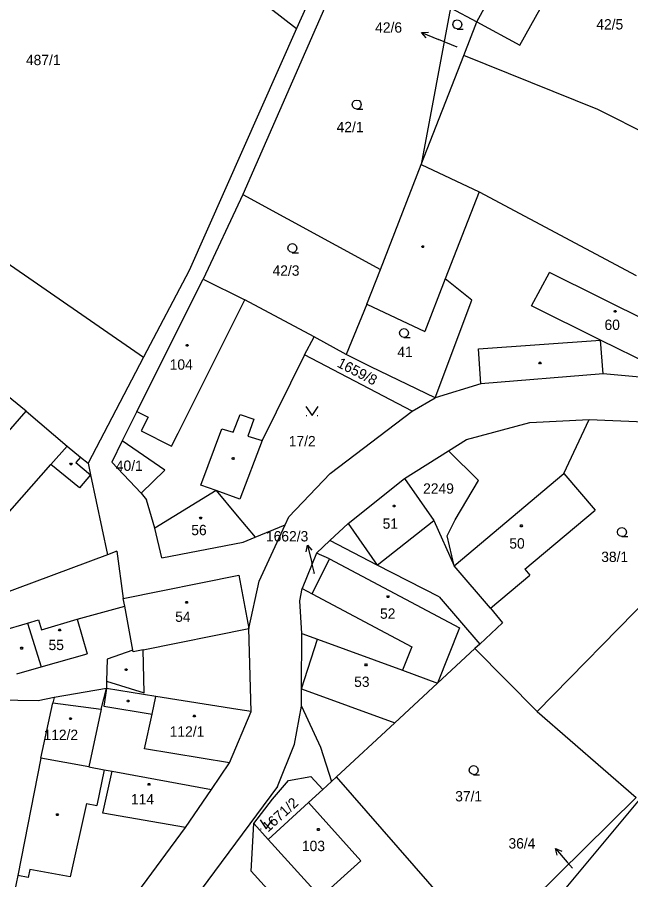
# Model space of a CAD drawing. Extents: x -802857 to -799647, y -1020285 to -1015884.
# Drawn here: x -801708.7 to -801607.8, y -1017782.1 to -1017640.2 of the extents above; entities that cross this region are included whole.
import ezdxf

# ---------------------------------------------------------------- set-up
doc = ezdxf.new("R2010")
doc.units = 0
for name, color, linetype in [('Default', 7, 'Continuous'), ('KN_HRANICE', 7, 'Continuous'), ('KN_KULTURY', 7, 'Continuous'), ('KN_PARCELY', 7, 'Continuous'), ('KN_SLUCKY', 7, 'Continuous')]:
    doc.layers.add(name, color=color, linetype=linetype)

# ---------------------------------------------------------------- blocks, each defined once
blk = doc.blocks.new('304')
at = {"layer": 'Default'}
blk.add_lwpolyline([(0, 0), (-0.38, 0.1), (-0.65, 0.37), (-0.75, 0.74), (-0.65, 1.11), (-0.38, 1.38), (-0.01, 1.48), (0.36, 1.38), (0.63, 1.11), (0.73, 0.73), (0.63, 0.35), (0.36, 0.08), (-0.02, -0.02), (0.98, -0.02)], dxfattribs=at)
blk = doc.blocks.new('314')
at = {"layer": 'Default'}
for p, q in [((-0.95, 0), (-0.85, 0)), ((0.85, 0), (0.95, 0))]:
    blk.add_line(p, q, dxfattribs=at)
blk.add_lwpolyline([(-1, 1.5), (0, 0), (1, 1.5)], dxfattribs=at)
blk = doc.blocks.new('NAHRADNI_SYMBOL')
at = {"layer": 'Default'}
blk.add_lwpolyline([(0.09, 0.15), (0.18, 0), (0.09, -0.15), (-0.09, -0.15), (-0.18, 0), (-0.09, 0.15), (0.09, 0.15)], dxfattribs=at)
blk = doc.blocks.new('10292')
at = {"layer": 'Default'}
blk.add_line((0, 3), (0, 0), dxfattribs=at)
blk.add_lwpolyline([(-0.5, 2), (0, 3), (0.5, 2)], dxfattribs=at)
blk = doc.blocks.new('402')
at = {"layer": 'Default'}
blk.add_lwpolyline([(0.09, 0.15), (0.18, 0), (0.09, -0.15), (-0.09, -0.15), (-0.18, 0), (-0.09, 0.15), (0.09, 0.15)], dxfattribs=at)

msp = doc.modelspace()

# ---------------------------------------------------------------- linework, layer by layer
at = {"layer": 'KN_HRANICE'}
for p, q in [((-801694.39, -1017617.48), (-801662.74, -1017642.08)), ((-801654.11, -1017629.4), (-801671.57, -1017669.41)), ((-801626.01, -1017644.85), (-801618.78, -1017631.82)), ((-801659.97, -1017635.92), (-801662.74, -1017642.08)), ((-801637.41, -1017638.71), (-801642.23, -1017664.46)), ((-801637.41, -1017638.71), (-801633.09, -1017641.02)), ((-801635.24, -1017646.54), (-801633.09, -1017641.02)), ((-801633.09, -1017641.02), (-801626.01, -1017644.85)), ((-801662.74, -1017642.08), (-801680.42, -1017681.9)), ((-801642.23, -1017664.46), (-801635.24, -1017646.54)), ((-801613.19, -1017655.4), (-801635.24, -1017646.54)), ((-801746.02, -1017656.03), (-801687.92, -1017696.18)), ((-801602.44, -1017660.83), (-801613.19, -1017655.4)), ((-801648.97, -1017681.75), (-801642.23, -1017664.46)), ((-801642.23, -1017664.46), (-801632.7, -1017668.98)), ((-801671.57, -1017669.41), (-801678.12, -1017683.31)), ((-801671.57, -1017669.41), (-801648.97, -1017681.75)), ((-801632.7, -1017668.98), (-801606.86, -1017682.7)), ((-801680.42, -1017681.9), (-801687.92, -1017696.18)), ((-801651.19, -1017687.43), (-801648.97, -1017681.75)), ((-801689.02, -1017705.11), (-801678.12, -1017683.31)), ((-801678.12, -1017683.31), (-801671.27, -1017686.73)), ((-801638.28, -1017683.28), (-801641.66, -1017691.95)), ((-801633.9, -1017686.78), (-801638.28, -1017683.28)), ((-801659.87, -1017692.82), (-801671.27, -1017686.73)), ((-801639.95, -1017702.84), (-801633.9, -1017686.78)), ((-801651.19, -1017687.43), (-801654.58, -1017695.71)), ((-801651.19, -1017687.43), (-801641.66, -1017691.95)), ((-801661.47, -1017695.76), (-801659.87, -1017692.82)), ((-801654.58, -1017695.71), (-801659.87, -1017692.82)), ((-801661.47, -1017695.76), (-801668.42, -1017709.88)), ((-801643.76, -1017705.03), (-801661.47, -1017695.76)), ((-801650.51, -1017697.72), (-801654.58, -1017695.71)), ((-801687.92, -1017696.18), (-801697.06, -1017713.57)), ((-801707.22, -1017705.04), (-801715, -1017698.75)), ((-801639.95, -1017702.84), (-801650.51, -1017697.72)), ((-801612.31, -1017698.9), (-801632.42, -1017700.52)), ((-801599.1, -1017700.11), (-801612.31, -1017698.9)), ((-801632.42, -1017700.52), (-801639.95, -1017702.84)), ((-801643.76, -1017705.03), (-801639.95, -1017702.84)), ((-801707.22, -1017705.04), (-801700.51, -1017710.77)), ((-801689.02, -1017705.11), (-801691.42, -1017709.92)), ((-801657.25, -1017715.27), (-801643.76, -1017705.03)), ((-801634.78, -1017709.68), (-801624.37, -1017706.9)), ((-801624.37, -1017706.9), (-801614.64, -1017706.43)), ((-801618.81, -1017715.29), (-801614.64, -1017706.43)), ((-801614.64, -1017706.43), (-801605.52, -1017706.8)), ((-801691.42, -1017709.92), (-801693.16, -1017713.42)), ((-801684.4, -1017714.76), (-801691.42, -1017709.92)), ((-801668.42, -1017709.88), (-801672.08, -1017719.51)), ((-801637.74, -1017711.55), (-801634.78, -1017709.68)), ((-801700.51, -1017710.77), (-801698.31, -1017712.61)), ((-801698.31, -1017712.61), (-801697.06, -1017713.57)), ((-801644.97, -1017716.12), (-801637.74, -1017711.55)), ((-801632.83, -1017716.42), (-801637.74, -1017711.55)), ((-801697.06, -1017713.57), (-801696.65, -1017715.5)), ((-801693.16, -1017713.42), (-801688.31, -1017718.52)), ((-801696.65, -1017715.5), (-801693.84, -1017728.66)), ((-801688.31, -1017718.52), (-801684.4, -1017714.76)), ((-801664.02, -1017722.44), (-801657.25, -1017715.27)), ((-801618.81, -1017715.29), (-801613.64, -1017721.3)), ((-801654.28, -1017723.49), (-801644.97, -1017716.12)), ((-801644.97, -1017716.12), (-801640.18, -1017723)), ((-801636.65, -1017722.91), (-801632.83, -1017716.42)), ((-801688.31, -1017718.52), (-801687.42, -1017719.63)), ((-801676, -1017718.11), (-801686.05, -1017724.27)), ((-801676, -1017718.11), (-801672.54, -1017722.24)), ((-801672.08, -1017719.51), (-801676, -1017718.11)), ((-801686.05, -1017724.27), (-801687.42, -1017719.63)), ((-801625.19, -1017731.05), (-801613.64, -1017721.3)), ((-801672.54, -1017722.24), (-801669.57, -1017725.78)), ((-801664.62, -1017723.74), (-801664.02, -1017722.44)), ((-801684.89, -1017729.17), (-801686.05, -1017724.27)), ((-801669.57, -1017725.78), (-801664.62, -1017723.74)), ((-801668.93, -1017733.02), (-801664.62, -1017723.74)), ((-801657.27, -1017726.33), (-801654.28, -1017723.49)), ((-801640.18, -1017723), (-801636.81, -1017730.48)), ((-801637.99, -1017725.54), (-801636.65, -1017722.91)), ((-801636.81, -1017730.48), (-801637.99, -1017725.54)), ((-801684.89, -1017729.17), (-801671.54, -1017726.59)), ((-801671.54, -1017726.59), (-801669.57, -1017725.78)), ((-801659.45, -1017728.4), (-801657.27, -1017726.33)), ((-801649.49, -1017730.37), (-801657.27, -1017726.33)), ((-801692.32, -1017728.09), (-801693.84, -1017728.66)), ((-801692.32, -1017728.09), (-801691.26, -1017735.85)), ((-801659.45, -1017728.4), (-801661.85, -1017734.23)), ((-801657.36, -1017729.32), (-801659.45, -1017728.4)), ((-801597.05, -1017727.73), (-801623.18, -1017754.46)), ((-801693.84, -1017728.66), (-801719.81, -1017738.32)), ((-801660.18, -1017735.09), (-801657.36, -1017729.32)), ((-801639.32, -1017735.57), (-801649.49, -1017730.37)), ((-801630.84, -1017737.46), (-801636.81, -1017730.48)), ((-801625.19, -1017731.05), (-801624.39, -1017732.01)), ((-801691.26, -1017735.85), (-801672.26, -1017732.02)), ((-801672.26, -1017732.02), (-801670.61, -1017740.8)), ((-801630.84, -1017737.46), (-801624.39, -1017732.01)), ((-801670.61, -1017740.8), (-801668.93, -1017733.02)), ((-801662.24, -1017736.26), (-801661.85, -1017734.23)), ((-801661.85, -1017734.23), (-801660.18, -1017735.09)), ((-801639.32, -1017735.57), (-801632.63, -1017743.34)), ((-801691.02, -1017737.09), (-801691.26, -1017735.85)), ((-801661.88, -1017741.62), (-801662.24, -1017736.26)), ((-801698.82, -1017739.23), (-801691.02, -1017737.09)), ((-801689.66, -1017744.35), (-801691.02, -1017737.09)), ((-801630.84, -1017737.46), (-801628.85, -1017739.85)), ((-801711.1, -1017741.13), (-801707, -1017739.9)), ((-801707, -1017739.9), (-801705.23, -1017739.37)), ((-801705.23, -1017739.37), (-801704.71, -1017740.98)), ((-801704.71, -1017740.98), (-801698.82, -1017739.23)), ((-801628.85, -1017739.85), (-801632.63, -1017743.34)), ((-801670.22, -1017754.45), (-801670.61, -1017740.8)), ((-801661.93, -1017750.69), (-801661.88, -1017741.62)), ((-801661.88, -1017741.62), (-801659.31, -1017742.56)), ((-801659.31, -1017742.56), (-801645.35, -1017747.65)), ((-801633.4, -1017744.06), (-801639.56, -1017749.76)), ((-801632.63, -1017743.34), (-801633.4, -1017744.06)), ((-801633.4, -1017744.06), (-801623.18, -1017754.46)), ((-801689.66, -1017744.35), (-801693.92, -1017745.81)), ((-801693.92, -1017745.81), (-801694.01, -1017749.47)), ((-801587.49, -1017746.18), (-801629.02, -1017796.14)), ((-801645.35, -1017747.65), (-801639.56, -1017749.76)), ((-801694.01, -1017749.47), (-801694.04, -1017750.65)), ((-801639.56, -1017749.76), (-801646.6, -1017756.28)), ((-801694.04, -1017750.65), (-801702.65, -1017752.12)), ((-801694.87, -1017754.03), (-801694.04, -1017750.65)), ((-801685.92, -1017751.95), (-801694.04, -1017750.65)), ((-801661.95, -1017753.57), (-801661.93, -1017750.69)), ((-801705.26, -1017752.69), (-801716.23, -1017752.46)), ((-801702.65, -1017752.12), (-801705.26, -1017752.69)), ((-801702.65, -1017752.12), (-801702.84, -1017753.01)), ((-801672.43, -1017754.12), (-801685.92, -1017751.95)), ((-801704.8, -1017762.14), (-801702.84, -1017753.01)), ((-801694.87, -1017754.03), (-801696.92, -1017763.53)), ((-801663.09, -1017759.81), (-801661.95, -1017753.57)), ((-801661.95, -1017753.57), (-801658.82, -1017760.33)), ((-801673.8, -1017762.87), (-801670.22, -1017754.45)), ((-801670.22, -1017754.45), (-801672.43, -1017754.12)), ((-801623.18, -1017754.46), (-801606.88, -1017768.59)), ((-801646.6, -1017756.28), (-801656.2, -1017765.17)), ((-801665.9, -1017766.77), (-801663.09, -1017759.81)), ((-801658.82, -1017760.33), (-801657.03, -1017765.95)), ((-801704.8, -1017762.14), (-801708.61, -1017781.39)), ((-801696.92, -1017763.53), (-801704.8, -1017762.14)), ((-801696.92, -1017763.53), (-801694.4, -1017764.02)), ((-801694.4, -1017764.02), (-801693.09, -1017764.26)), ((-801676.76, -1017767.27), (-801673.8, -1017762.87)), ((-801693.09, -1017764.26), (-801676.76, -1017767.27)), ((-801664.1, -1017765.81), (-801660.39, -1017765.12)), ((-801660.39, -1017765.12), (-801658.43, -1017767.26)), ((-801657.03, -1017765.95), (-801656.2, -1017765.17)), ((-801636.53, -1017787.69), (-801656.2, -1017765.17)), ((-801665.9, -1017766.77), (-801692.56, -1017802.78)), ((-801666.69, -1017768.84), (-801664.1, -1017765.81)), ((-801658.43, -1017767.26), (-801657.03, -1017765.95)), ((-801681, -1017773.54), (-801676.76, -1017767.27)), ((-801658.43, -1017767.26), (-801660.79, -1017769.42)), ((-801669.76, -1017772.89), (-801666.69, -1017768.84)), ((-801667.4, -1017775.47), (-801660.79, -1017769.42)), ((-801606.88, -1017768.59), (-801631.76, -1017793.06)), ((-801694.1, -1017791.18), (-801681, -1017773.54)), ((-801670.22, -1017780.7), (-801669.76, -1017772.89)), ((-801669.76, -1017772.89), (-801667.4, -1017775.47)), ((-801658.84, -1017785), (-801667.4, -1017775.47)), ((-801670.22, -1017780.7), (-801652.82, -1017799.83)), ((-801708.61, -1017781.39), (-801709.16, -1017784.06))]:
    msp.add_line(p, q, dxfattribs=at)
at = {"layer": 'KN_PARCELY'}
for p, q in [((-801636.33, -1017645.16), (-801639.4, -1017643.91)), ((-801659.81, -1017731.72), (-801660.23, -1017729.99)), ((-801617.36, -1017780.23), (-801618.21, -1017779.25))]:
    msp.add_line(p, q, dxfattribs=at)
at = {"layer": 'KN_SLUCKY'}
for p, q in [((-801633.09, -1017641.02), (-801626.1, -1017628.02)), ((-801632.7, -1017668.98), (-801638.28, -1017683.28)), ((-801624.08, -1017687.71), (-801621.15, -1017682.25)), ((-801596.17, -1017694.65), (-801621.15, -1017682.25)), ((-801682.23, -1017708.65), (-801671.27, -1017686.73)), ((-801612.74, -1017693.34), (-801624.08, -1017687.71)), ((-801632.84, -1017694.8), (-801612.74, -1017693.34)), ((-801612.31, -1017698.9), (-801612.74, -1017693.34)), ((-801599.1, -1017700.11), (-801612.74, -1017693.34)), ((-801632.42, -1017700.52), (-801632.84, -1017694.8)), ((-801717.85, -1017717.14), (-801707.22, -1017705.04)), ((-801689.02, -1017705.11), (-801687.18, -1017706.03)), ((-801673.18, -1017708.52), (-801672.05, -1017705.58)), ((-801672.05, -1017705.58), (-801669.78, -1017706.35)), ((-801687.18, -1017706.03), (-801688.31, -1017708.29)), ((-801669.78, -1017706.35), (-801670.76, -1017709.13)), ((-801688.31, -1017708.29), (-801683.3, -1017710.79)), ((-801683.3, -1017710.79), (-801682.23, -1017708.65)), ((-801678.52, -1017717.22), (-801675.04, -1017707.92)), ((-801675.04, -1017707.92), (-801673.18, -1017708.52)), ((-801670.76, -1017709.13), (-801668.42, -1017709.88)), ((-801703.2, -1017713.83), (-801700.51, -1017710.77)), ((-801698.31, -1017712.61), (-801699.07, -1017713.49)), ((-801711.14, -1017722.87), (-801703.2, -1017713.83)), ((-801698.46, -1017717.66), (-801703.2, -1017713.83)), ((-801699.07, -1017713.49), (-801696.65, -1017715.5)), ((-801696.65, -1017715.5), (-801698.46, -1017717.66)), ((-801636.81, -1017730.48), (-801618.81, -1017715.29)), ((-801676, -1017718.11), (-801678.52, -1017717.22)), ((-801654.28, -1017723.49), (-801649.49, -1017730.37)), ((-801649.49, -1017730.37), (-801640.18, -1017723)), ((-801657.36, -1017729.32), (-801635.93, -1017740.7)), ((-801660.18, -1017735.09), (-801643.8, -1017743.79)), ((-801707, -1017739.9), (-801704.74, -1017747.09)), ((-801698.82, -1017739.23), (-801697.22, -1017744.93)), ((-801687.96, -1017744.3), (-801670.61, -1017740.8)), ((-801635.93, -1017740.7), (-801639.56, -1017749.76)), ((-801661.93, -1017750.69), (-801659.31, -1017742.56)), ((-801643.8, -1017743.79), (-801645.35, -1017747.65)), ((-801704.74, -1017747.09), (-801697.22, -1017744.93)), ((-801689.61, -1017744.63), (-801689.66, -1017744.35)), ((-801687.96, -1017744.3), (-801689.61, -1017744.63)), ((-801687.8, -1017751.37), (-801687.96, -1017744.3)), ((-801708.79, -1017748.25), (-801704.74, -1017747.09)), ((-801694.01, -1017749.47), (-801687.8, -1017751.37)), ((-801694.04, -1017750.65), (-801694.46, -1017753.56)), ((-801661.93, -1017750.69), (-801646.6, -1017756.28)), ((-801686.53, -1017754.87), (-801685.92, -1017751.95)), ((-801702.84, -1017753.01), (-801694.87, -1017754.03)), ((-801694.46, -1017753.56), (-801686.53, -1017754.87)), ((-801687.74, -1017760.59), (-801686.53, -1017754.87)), ((-801673.8, -1017762.87), (-801687.74, -1017760.59)), ((-801694.4, -1017764.02), (-801695.62, -1017769.88)), ((-801694.61, -1017771.15), (-801693.09, -1017764.26)), ((-801697.33, -1017769.56), (-801699.98, -1017781.66)), ((-801697.33, -1017769.56), (-801695.62, -1017769.88)), ((-801660.79, -1017769.42), (-801652.2, -1017779.01)), ((-801681, -1017773.54), (-801694.61, -1017771.15)), ((-801652.2, -1017779.01), (-801658.84, -1017785)), ((-801706.65, -1017780.44), (-801706.91, -1017781.74)), ((-801699.98, -1017781.66), (-801706.65, -1017780.44)), ((-801706.91, -1017781.74), (-801708.61, -1017781.39))]:
    msp.add_line(p, q, dxfattribs=at)

# ---------------------------------------------------------------- block references
at = {"layer": 'KN_KULTURY'}
for name, p in [('304', (-801636.31, -1017642.16)), ('304', (-801652.84, -1017655.34)), ('304', (-801663.43, -1017678.95)), ('402', (-801641.99, -1017677.99)), ('402', (-801610.34, -1017688.61)), ('304', (-801645.06, -1017692.91)), ('402', (-801680.74, -1017694.22)), ('402', (-801622.7, -1017697.11)), ('314', (-801660.2, -1017705.75)), ('402', (-801673.19, -1017712.82)), ('402', (-801699.87, -1017713.73)), ('402', (-801646.69, -1017720.65)), ('NAHRADNI_SYMBOL', (-801678.54, -1017722.62)), ('402', (-801625.79, -1017723.89)), ('304', (-801609.23, -1017725.66)), ('402', (-801647.71, -1017735.56)), ('402', (-801680.84, -1017736.48)), ('402', (-801701.71, -1017741.02)), ('402', (-801707.97, -1017744.01)), ('402', (-801651.34, -1017746.77)), ('402', (-801690.78, -1017747.56)), ('402', (-801690.45, -1017752.71)), ('402', (-801699.93, -1017755.62)), ('402', (-801679.56, -1017755.17)), ('304', (-801633.62, -1017764.82)), ('402', (-801687.03, -1017766.41)), ('402', (-801702.11, -1017771.41)), ('314', (-801667.75, -1017773.75)), ('402', (-801659.16, -1017773.85))]:
    msp.add_blockref(name, p, dxfattribs=at)
at = {"layer": 'KN_PARCELY'}
for p, rotation in [((-801639.4, -1017643.91), 67.83820300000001), ((-801660.23, -1017729.99), 13.693691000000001), ((-801618.21, -1017779.25), 40.851890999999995)]:
    msp.add_blockref('10292', p, dxfattribs=dict(at, rotation=rotation))

# ---------------------------------------------------------------- texts
for s, height, p in [('42/5', 1.7, (-801613.44, -1017642.26)), ('42/6', 1.7, (-801649.82, -1017642.78)), ('42/6', 0.1, (-801636.53, -1017645.16)), ('487/1', 1.7, (-801707.27, -1017648.12)), ('42/1', 1.7, (-801656.16, -1017659.15)), ('42/3', 1.7, (-801666.7, -1017682.76)), ('60', 1.7, (-801612.09, -1017691.68)), ('41', 1.7, (-801646.17, -1017696.13)), ('104', 1.7, (-801683.62, -1017698.22)), ('17/2', 1.7, (-801664.03, -1017710.82)), ('40/1', 1.7, (-801692.48, -1017714.86)), ('2249', 1.7, (-801641.93, -1017718.61)), ('51', 1.7, (-801648.59, -1017724.38)), ('56', 1.7, (-801680.07, -1017725.44)), ('1662/3', 1.7, (-801667.78, -1017726.47)), ('50', 1.7, (-801627.75, -1017727.64)), ('38/1', 1.7, (-801612.63, -1017729.85)), ('1662/3', 0.1, (-801660.11, -1017731.72)), ('54', 1.7, (-801682.72, -1017739.7)), ('52', 1.7, (-801649.02, -1017739.19)), ('55', 1.7, (-801703.55, -1017744.34)), ('53', 1.7, (-801653.28, -1017750.4)), ('112/1', 1.7, (-801683.62, -1017758.58)), ('112/2', 1.7, (-801704.38, -1017759.13)), ('114', 1.7, (-801689.99, -1017769.73)), ('37/1', 1.7, (-801636.65, -1017769.23)), ('36/4', 1.7, (-801627.89, -1017776.98)), ('103', 1.7, (-801661.87, -1017777.41)), ('36/4', 0.1, (-801617.56, -1017780.23))]:
    msp.add_text(s, height=height, dxfattribs=at).set_placement(p)
for s, rotation, p in [('1659/8', 332.659, (-801656.23, -1017697.66)), ('1671/2', 42.112, (-801667.45, -1017774.36))]:
    msp.add_text(s, height=1.7, rotation=rotation, dxfattribs=at).set_placement(p)

doc.saveas('drawing.dxf')
